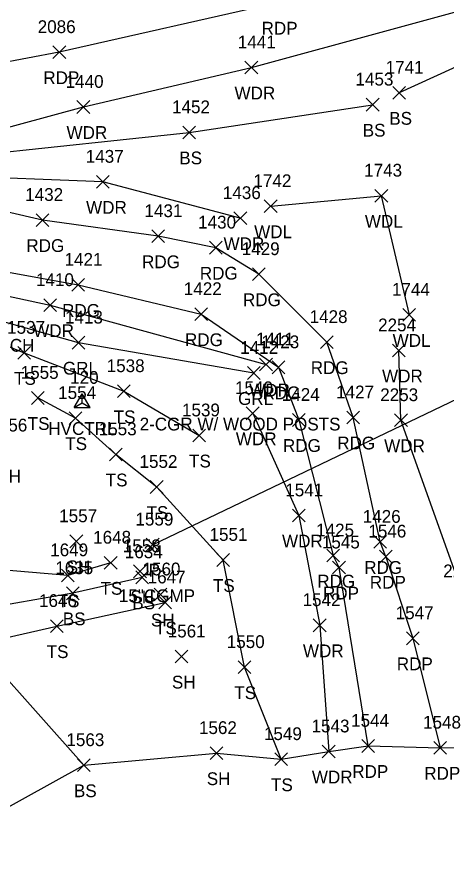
# Model space of a CAD drawing. Extents: x 1526508 to 1531550, y 369926 to 373082.
# Drawn here: x 1531075.3 to 1531142.8, y 370009.2 to 370143.1 of the extents above; entities that cross this region are included whole.
import ezdxf

# ---------------------------------------------------------------- set-up
doc = ezdxf.new("R2010")
doc.units = 0
for name, color, linetype in [('C_A', 7, 'Continuous'), ('C_I', 7, 'Continuous'), ('CPSM', 7, 'Continuous'), ('D_A', 7, 'Continuous'), ('D_C', 7, 'Continuous'), ('D_I', 7, 'Continuous'), ('D_TIC', 7, 'Continuous'), ('DCP', 7, 'Continuous'), ('L_A', 7, 'Continuous'), ('L_I', 7, 'Continuous'), ('L_TIC', 7, 'Continuous'), ('LAWA', 7, 'Continuous'), ('LELB', 7, 'Continuous'), ('LSOGP', 7, 'Continuous'), ('P_A', 7, 'Continuous'), ('P_I', 7, 'Continuous'), ('P_TIC', 7, 'Continuous'), ('PET', 7, 'Continuous'), ('PEU', 7, 'Continuous'), ('R_A', 7, 'Continuous'), ('R_C', 7, 'Continuous'), ('R_I', 7, 'Continuous'), ('R_TIC', 7, 'Continuous'), ('RGR', 7, 'Continuous')]:
    doc.layers.add(name, color=color, linetype=linetype)

msp = doc.modelspace()

# ---------------------------------------------------------------- linework, layer by layer
at = {"layer": 'CPSM'}
for p, q in [((1531084.3, 370081.95), (1531085.55, 370084.11)), ((1531086.8, 370081.95), (1531085.55, 370084.11)), ((1531085.55, 370082.67), (1531085.55, 370084.11)), ((1531084.3, 370081.95), (1531085.55, 370082.67)), ((1531084.3, 370081.95), (1531086.8, 370081.95)), ((1531085.55, 370082.67), (1531085.55, 370082.67)), ((1531085.55, 370082.67), (1531086.8, 370081.95))]:
    msp.add_line(p, q, dxfattribs=at)
at = {"layer": 'D_TIC'}
for points in [[(1531095.61, 370059.47), (1531097.61, 370061.47)], [(1531097.61, 370059.47), (1531095.61, 370061.47)]]:
    msp.add_lwpolyline(points, dxfattribs=at)
at = {"layer": 'DCP'}
msp.add_lwpolyline([(1531096.61, 370060.47), (1531148.27, 370085.19)], dxfattribs=at)
at = {"layer": 'L_TIC'}
for points in [[(1531111.09, 370134.21), (1531113.09, 370136.21)], [(1531113.09, 370134.21), (1531111.09, 370136.21)], [(1531134.28, 370130.25), (1531136.28, 370132.25)], [(1531136.28, 370130.25), (1531134.28, 370132.25)], [(1531084.74, 370128.03), (1531086.74, 370130.03)], [(1531086.74, 370128.03), (1531084.74, 370130.03)], [(1531130.11, 370128.39), (1531132.11, 370130.39)], [(1531132.11, 370128.39), (1531130.11, 370130.39)], [(1531101.35, 370124.05), (1531103.35, 370126.05)], [(1531103.35, 370124.05), (1531101.35, 370126.05)], [(1531087.81, 370116.3), (1531089.81, 370118.3)], [(1531089.81, 370116.3), (1531087.81, 370118.3)], [(1531131.47, 370114.13), (1531133.47, 370116.13)], [(1531133.47, 370114.13), (1531131.47, 370116.13)], [(1531114.12, 370112.48), (1531116.12, 370114.48)], [(1531116.12, 370112.48), (1531114.12, 370114.48)], [(1531109.36, 370110.61), (1531111.36, 370112.61)], [(1531111.36, 370110.61), (1531109.36, 370112.61)], [(1531079.52, 370096.98), (1531081.52, 370098.98)], [(1531081.52, 370096.98), (1531079.52, 370098.98)], [(1531135.83, 370095.46), (1531137.83, 370097.46)], [(1531137.83, 370095.46), (1531135.83, 370097.46)], [(1531075.47, 370089.51), (1531077.47, 370091.51)], [(1531077.47, 370089.51), (1531075.47, 370091.51)], [(1531134.23, 370089.89), (1531136.23, 370091.89)], [(1531136.23, 370089.89), (1531134.23, 370091.89)], [(1531113.39, 370087.68), (1531115.39, 370089.68)], [(1531115.39, 370087.68), (1531113.39, 370089.68)], [(1531091.09, 370083.5), (1531093.09, 370085.5)], [(1531093.09, 370083.5), (1531091.09, 370085.5)], [(1531077.61, 370082.45), (1531079.61, 370084.45)], [(1531079.61, 370082.45), (1531077.61, 370084.45)], [(1531111.3, 370080.05), (1531113.3, 370082.05)], [(1531113.3, 370080.05), (1531111.3, 370082.05)], [(1531083.49, 370079.29), (1531085.49, 370081.29)], [(1531085.49, 370079.29), (1531083.49, 370081.29)], [(1531134.56, 370078.96), (1531136.56, 370080.96)], [(1531136.56, 370078.96), (1531134.56, 370080.96)], [(1531102.91, 370076.57), (1531104.91, 370078.57)], [(1531104.91, 370076.57), (1531102.91, 370078.57)], [(1531089.84, 370073.6), (1531091.84, 370075.6)], [(1531091.84, 370073.6), (1531089.84, 370075.6)], [(1531096.24, 370068.5), (1531098.24, 370070.5)], [(1531098.24, 370068.5), (1531096.24, 370070.5)], [(1531118.54, 370064.04), (1531120.54, 370066.04)], [(1531120.54, 370064.04), (1531118.54, 370066.04)], [(1531083.64, 370059.99), (1531085.64, 370061.99)], [(1531085.64, 370059.99), (1531083.64, 370061.99)], [(1531106.66, 370057.07), (1531108.66, 370059.07)], [(1531108.66, 370057.07), (1531106.66, 370059.07)], [(1531089.02, 370056.63), (1531091.02, 370058.63)], [(1531091.02, 370056.63), (1531089.02, 370058.63)], [(1531082.29, 370054.66), (1531084.29, 370056.66)], [(1531084.29, 370054.66), (1531082.29, 370056.66)], [(1531093.63, 370055.29), (1531095.63, 370057.29)], [(1531095.63, 370055.29), (1531093.63, 370057.29)], [(1531093.98, 370054.35), (1531095.98, 370056.35)], [(1531095.98, 370054.35), (1531093.98, 370056.35)], [(1531083.08, 370051.85), (1531085.08, 370053.85)], [(1531085.08, 370051.85), (1531083.08, 370053.85)], [(1531096.85, 370051.66), (1531098.85, 370053.66)], [(1531098.85, 370051.66), (1531096.85, 370053.66)], [(1531097.57, 370050.41), (1531099.57, 370052.41)], [(1531099.57, 370050.41), (1531097.57, 370052.41)], [(1531080.58, 370046.71), (1531082.58, 370048.71)], [(1531082.58, 370046.71), (1531080.58, 370048.71)], [(1531121.81, 370046.84), (1531123.81, 370048.84)], [(1531123.81, 370046.84), (1531121.81, 370048.84)], [(1531100.14, 370041.94), (1531102.14, 370043.94)], [(1531102.14, 370041.94), (1531100.14, 370043.94)], [(1531110.01, 370040.28), (1531112.01, 370042.28)], [(1531112.01, 370040.28), (1531110.01, 370042.28)], [(1531105.61, 370026.81), (1531107.61, 370028.81)], [(1531107.61, 370026.81), (1531105.61, 370028.81)], [(1531115.76, 370025.86), (1531117.76, 370027.86)], [(1531117.76, 370025.86), (1531115.76, 370027.86)], [(1531123.22, 370027.07), (1531125.22, 370029.07)], [(1531125.22, 370027.07), (1531123.22, 370029.07)], [(1531084.82, 370024.92), (1531086.82, 370026.92)], [(1531086.82, 370024.92), (1531084.82, 370026.92)]]:
    msp.add_lwpolyline(points, dxfattribs=at)
at = {"layer": 'LAWA'}
for points in [[(1531110.36, 370111.61), (1531088.81, 370117.3), (1531064.64, 370118.26), (1531064.75, 370123.38), (1531085.74, 370129.03), (1531112.09, 370135.21), (1531155.65, 370147.14), (1531210.22, 370163.6)], [(1531115.12, 370113.48), (1531132.47, 370115.13), (1531136.83, 370096.46)], [(1530968.16, 370037.39), (1530979.88, 370048.99), (1530990.04, 370057.09), (1531002.64, 370070.87), (1531012.13, 370088.18), (1531024.74, 370101.61), (1531031.26, 370108.89), (1531038.68, 370107.68), (1531051.11, 370105.81), (1531063.82, 370101.61), (1531080.52, 370097.98), (1531114.39, 370088.68)], [(1531148.63, 370028.78), (1531145.43, 370052.36), (1531135.56, 370079.96), (1531135.23, 370090.89)], [(1531112.3, 370081.05), (1531119.54, 370065.04), (1531122.81, 370047.84), (1531124.22, 370028.07)]]:
    msp.add_lwpolyline(points, dxfattribs=at)
at = {"layer": 'LELB'}
for points in [[(1531210.97, 370157.64), (1531190.22, 370151.95), (1531176.55, 370148.6), (1531161.06, 370141.76), (1531149.58, 370137.75), (1531135.28, 370131.25)], [(1531069.83, 370121.59), (1531102.35, 370125.05), (1531131.11, 370129.39)], [(1531048.19, 370101.74), (1531053.87, 370099.46), (1531064.2, 370095.53), (1531076.47, 370090.51), (1531092.09, 370084.5), (1531103.91, 370077.57)], [(1531116.76, 370026.86), (1531111.01, 370041.28), (1531107.66, 370058.07), (1531097.24, 370069.5), (1531090.84, 370074.6), (1531084.49, 370080.29), (1531078.61, 370083.45)], [(1531090.02, 370057.63), (1531083.29, 370055.66), (1531071.52, 370056.63), (1531058.8, 370052.34), (1531046.74, 370046.89), (1531038.82, 370043.78), (1531032.45, 370035.18)], [(1531094.98, 370055.35), (1531084.08, 370052.85), (1531072.11, 370050.78), (1531058.12, 370045.91), (1531045.19, 370040.43), (1531041.55, 370031.59), (1531036.79, 370023.06)], [(1531041.79, 370021.67), (1531045.24, 370029.7), (1531051.72, 370039.49), (1531060.58, 370042.81), (1531072.12, 370045.58), (1531081.58, 370047.71), (1531098.57, 370051.41)], [(1531085.82, 370025.92), (1531071.43, 370042.02)]]:
    msp.add_lwpolyline(points, dxfattribs=at)
at = {"layer": 'LSOGP'}
msp.add_lwpolyline([(1531057.51, 369997.2), (1531064.16, 370011.44), (1531071.32, 370017.92), (1531085.82, 370025.92), (1531106.61, 370027.81), (1531116.76, 370026.86), (1531124.22, 370028.07), (1531130.42, 370028.94), (1531141.72, 370028.66), (1531148.63, 370028.78)], dxfattribs=at)
at = {"layer": 'P_TIC'}
for points in [[(1531080.97, 370136.61), (1531082.97, 370138.61)], [(1531082.97, 370136.61), (1531080.97, 370138.61)], [(1531078.32, 370110.32), (1531080.32, 370112.32)], [(1531080.32, 370110.32), (1531078.32, 370112.32)], [(1531096.46, 370107.78), (1531098.46, 370109.78)], [(1531098.46, 370107.78), (1531096.46, 370109.78)], [(1531105.52, 370105.99), (1531107.52, 370107.99)], [(1531107.52, 370105.99), (1531105.52, 370107.99)], [(1531112.28, 370101.83), (1531114.28, 370103.83)], [(1531114.28, 370101.83), (1531112.28, 370103.83)], [(1531083.92, 370100.16), (1531085.92, 370102.16)], [(1531085.92, 370100.16), (1531083.92, 370102.16)], [(1531103.2, 370095.57), (1531105.2, 370097.57)], [(1531105.2, 370095.57), (1531103.2, 370097.57)], [(1531122.92, 370091.19), (1531124.92, 370093.19)], [(1531124.92, 370091.19), (1531122.92, 370093.19)], [(1531115.34, 370087.25), (1531117.34, 370089.25)], [(1531117.34, 370087.25), (1531115.34, 370089.25)], [(1531118.55, 370079), (1531120.55, 370081)], [(1531120.55, 370079), (1531118.55, 370081)], [(1531127.07, 370079.39), (1531129.07, 370081.39)], [(1531129.07, 370079.39), (1531127.07, 370081.39)], [(1531131.31, 370059.9), (1531133.31, 370061.9)], [(1531133.31, 370059.9), (1531131.31, 370061.9)], [(1531123.94, 370057.76), (1531125.94, 370059.76)], [(1531125.94, 370057.76), (1531123.94, 370059.76)], [(1531132.18, 370057.59), (1531134.18, 370059.59)], [(1531134.18, 370057.59), (1531132.18, 370059.59)], [(1531124.84, 370055.88), (1531126.84, 370057.88)], [(1531126.84, 370055.88), (1531124.84, 370057.88)], [(1531136.41, 370044.8), (1531138.41, 370046.8)], [(1531138.41, 370044.8), (1531136.41, 370046.8)], [(1531129.42, 370027.94), (1531131.42, 370029.94)], [(1531131.42, 370027.94), (1531129.42, 370029.94)], [(1531140.72, 370027.66), (1531142.72, 370029.66)], [(1531142.72, 370027.66), (1531140.72, 370029.66)]]:
    msp.add_lwpolyline(points, dxfattribs=at)
at = {"layer": 'PET'}
for points in [[(1531538.54, 370286.02), (1531506.28, 370274.48), (1531462.76, 370259.55), (1531429.61, 370248.08), (1531393.11, 370234.63), (1531350.62, 370219.92), (1531310.67, 370205.95), (1531271.31, 370192.3), (1531228.45, 370178.01), (1531188.4, 370165.28), (1531155.96, 370155.78), (1531116.2, 370145.37), (1531081.97, 370137.61), (1531057.06, 370132.93), (1531039.15, 370130.45)], [(1531133.18, 370058.59), (1531132.31, 370060.9)], [(1531125.84, 370056.88), (1531124.94, 370058.76)], [(1531133.18, 370058.59), (1531137.41, 370045.8), (1531141.72, 370028.66)], [(1531130.42, 370028.94), (1531125.84, 370056.88)]]:
    msp.add_lwpolyline(points, dxfattribs=at)
at = {"layer": 'PEU'}
for points in [[(1531132.31, 370060.9), (1531128.07, 370080.39), (1531123.92, 370092.19), (1531113.28, 370102.83), (1531106.52, 370106.99), (1531097.46, 370108.78), (1531079.32, 370111.32), (1531068.68, 370113.74), (1531054.33, 370119.93), (1531056.08, 370131.31)], [(1531023.29, 370127.71), (1531040.68, 370118), (1531054.1, 370108.44), (1531069.6, 370103.94), (1531084.92, 370101.16), (1531104.2, 370096.57), (1531116.34, 370088.25), (1531119.55, 370080), (1531124.94, 370058.76)]]:
    msp.add_lwpolyline(points, dxfattribs=at)
at = {"layer": 'R_TIC'}
for points in [[(1531083.99, 370091.11), (1531085.99, 370093.11)], [(1531085.99, 370091.11), (1531083.99, 370093.11)], [(1531111.46, 370086.36), (1531113.46, 370088.36)], [(1531113.46, 370086.36), (1531111.46, 370088.36)]]:
    msp.add_lwpolyline(points, dxfattribs=at)
at = {"layer": 'RGR'}
msp.add_lwpolyline([(1531112.46, 370087.36), (1531084.99, 370092.11), (1531060.32, 370098.96), (1531044.48, 370104.76), (1531031.99, 370106.26)], dxfattribs=at)

# ---------------------------------------------------------------- texts
at = {"layer": 'C_A'}
msp.add_text('HVCTRL', height=2, dxfattribs=at).set_placement((1531080.24, 370077.67))
at = {"layer": 'C_I'}
msp.add_text('120', height=2, dxfattribs=at).set_placement((1531083.67, 370085.67))
at = {"layer": 'D_A'}
msp.add_text('P', height=2, dxfattribs=at).set_placement((1531095.99, 370055.47))
at = {"layer": 'D_C'}
for s, p in [("10'WIDE X 12'HIGH CONCRETE ARCH", (1531030.09, 370090.7)), ('15"CGMP', (1531091.31, 370051.47))]:
    msp.add_text(s, height=2, dxfattribs=at).set_placement(p)
at = {"layer": 'D_I'}
msp.add_text('1559', height=2, dxfattribs=at).set_placement((1531093.91, 370063.47))
at = {"layer": 'L_A'}
for s, p in [('WDR', (1531109.45, 370130.21)), ('BS', (1531133.72, 370126.25)), ('WDR', (1531083.1, 370124.03)), ('BS', (1531129.56, 370124.39)), ('BS', (1531100.79, 370120.05)), ('WDR', (1531086.17, 370112.3)), ('WDL', (1531129.89, 370110.13)), ('WDL', (1531112.53, 370108.48)), ('WDR', (1531107.73, 370106.61)), ('WDR', (1531077.88, 370092.98)), ('WDL', (1531134.25, 370091.46)), ('TS', (1531074.88, 370085.51)), ('WDR', (1531132.59, 370085.89)), ('WDR', (1531111.75, 370083.68)), ('TS', (1531090.5, 370079.5)), ('TS', (1531077.02, 370078.45)), ('WDR', (1531109.66, 370076.05)), ('TS', (1531082.9, 370075.29)), ('WDR', (1531132.92, 370074.96)), ('TS', (1531102.32, 370072.57)), ('SH', (1531072.23, 370070.2)), ('TS', (1531089.25, 370069.6)), ('TS', (1531095.65, 370064.5)), ('WDR', (1531116.9, 370060.04)), ('SH', (1531083.13, 370055.99)), ('TS', (1531088.43, 370052.63)), ('TS', (1531106.06, 370053.07)), ('SH', (1531093.12, 370051.29)), ('TS', (1531081.7, 370050.66)), ('BS', (1531093.42, 370050.35)), ('BS', (1531082.52, 370047.85)), ('SH', (1531096.34, 370047.66)), ('TS', (1531096.98, 370046.41)), ('TS', (1531079.99, 370042.71)), ('WDR', (1531120.18, 370042.84)), ('SH', (1531099.63, 370037.94)), ('TS', (1531109.42, 370036.28)), ('SH', (1531105.1, 370022.81)), ('TS', (1531115.17, 370021.86)), ('WDR', (1531121.58, 370023.07)), ('BS', (1531084.26, 370020.92))]:
    msp.add_text(s, height=2, dxfattribs=at).set_placement(p)
at = {"layer": 'L_I'}
for s, p in [('1441', (1531109.96, 370138.21)), ('1741', (1531133.15, 370134.25)), ('1440', (1531082.96, 370132.03)), ('1453', (1531128.42, 370132.39)), ('1452', (1531099.65, 370128.05)), ('1437', (1531086.12, 370120.3)), ('1743', (1531129.78, 370118.13)), ('1742', (1531112.42, 370116.48)), ('1436', (1531107.62, 370114.61)), ('1410', (1531078.31, 370100.98)), ('1744', (1531134.14, 370099.46)), ('1537', (1531073.78, 370093.51)), ('2254', (1531131.97, 370093.89)), ('1411', (1531112.83, 370091.68)), ('1538', (1531089.4, 370087.5)), ('1555', (1531075.91, 370086.45)), ('1540', (1531109.52, 370084.05)), ('1554', (1531081.79, 370083.29)), ('2253', (1531132.3, 370082.96)), ('1539', (1531101.21, 370080.57)), ('1556', (1531071, 370078.2)), ('1553', (1531088.15, 370077.6)), ('1552', (1531094.55, 370072.5)), ('1541', (1531117.41, 370068.04)), ('1557', (1531081.95, 370063.99)), ('1551', (1531105.53, 370061.07)), ('1648', (1531087.28, 370060.63)), ('1649', (1531080.54, 370058.66)), ('1558', (1531091.93, 370059.29)), ('1634', (1531092.24, 370058.35)), ('1635', (1531081.34, 370055.85)), ('1560', (1531095.02, 370055.66)), ('2252', (1531142.18, 370055.36)), ('1647', (1531095.83, 370054.41)), ('1646', (1531078.78, 370050.71)), ('1542', (1531120.12, 370050.84)), ('1561', (1531098.97, 370045.94)), ('1550', (1531108.23, 370044.28)), ('1562', (1531103.87, 370030.81)), ('1549', (1531114.06, 370029.86)), ('1543', (1531121.53, 370031.07)), ('1563', (1531083.08, 370028.92))]:
    msp.add_text(s, height=2, dxfattribs=at).set_placement(p)
at = {"layer": 'P_A'}
for s, p in [('RDP', (1531113.69, 370140.37)), ('RDP', (1531079.46, 370132.61)), ('RDG', (1531076.8, 370106.32)), ('RDG', (1531094.95, 370103.78)), ('RDG', (1531104.01, 370101.99)), ('RDG', (1531110.77, 370097.83)), ('RDG', (1531082.41, 370096.16)), ('RDG', (1531101.68, 370091.57)), ('RDG', (1531121.41, 370087.19)), ('RDG', (1531113.83, 370083.25)), ('RDG', (1531125.56, 370075.39)), ('RDG', (1531117.04, 370075)), ('RDG', (1531129.79, 370055.9)), ('RDG', (1531122.43, 370053.76)), ('RDP', (1531130.67, 370053.59)), ('RDP', (1531123.33, 370051.88)), ('RDP', (1531134.9, 370040.8)), ('RDP', (1531127.91, 370023.94)), ('RDP', (1531139.21, 370023.66))]:
    msp.add_text(s, height=2, dxfattribs=at).set_placement(p)
at = {"layer": 'P_I'}
for s, p in [('2086', (1531078.58, 370140.61)), ('1432', (1531076.62, 370114.32)), ('1431', (1531095.33, 370111.78)), ('1430', (1531103.74, 370109.99)), ('1429', (1531110.58, 370105.83)), ('1421', (1531082.79, 370104.16)), ('1422', (1531101.5, 370099.57)), ('1428', (1531121.23, 370095.19)), ('1423', (1531113.65, 370091.25)), ('1424', (1531116.86, 370083)), ('1427', (1531125.38, 370083.39)), ('1426', (1531129.56, 370063.9)), ('1425', (1531122.25, 370061.76)), ('1546', (1531130.44, 370061.59)), ('1545', (1531123.15, 370059.88)), ('1547', (1531134.72, 370048.8)), ('1544', (1531127.73, 370031.94)), ('1548', (1531139.02, 370031.66))]:
    msp.add_text(s, height=2, dxfattribs=at).set_placement(p)
at = {"layer": 'R_A'}
for p in [(1531082.53, 370087.11), (1531110, 370082.36)]:
    msp.add_text('GRL', height=2, dxfattribs=at).set_placement(p)
at = {"layer": 'R_C'}
msp.add_text('2-CGR W/ WOOD POSTS', height=2, dxfattribs=at).set_placement((1531094.57, 370078.36))
at = {"layer": 'R_I'}
for s, p in [('1413', (1531082.86, 370095.11)), ('1412', (1531110.34, 370090.36))]:
    msp.add_text(s, height=2, dxfattribs=at).set_placement(p)

doc.saveas('drawing.dxf')
